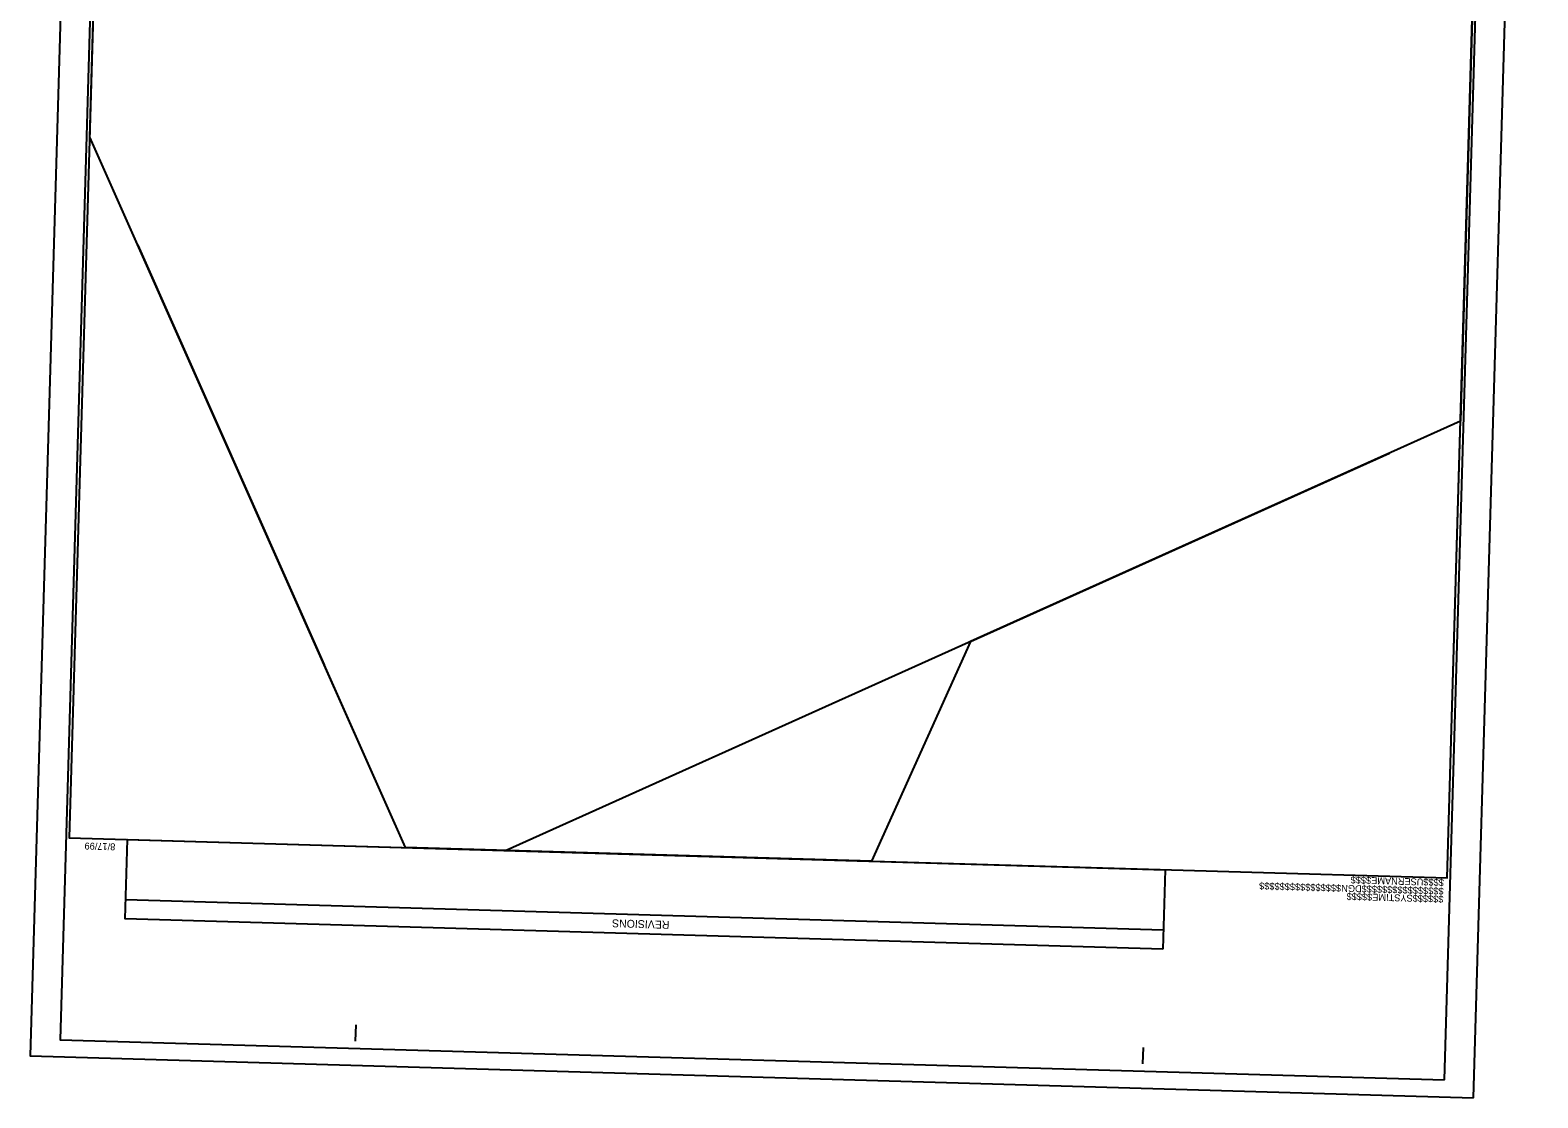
# Model space of a CAD drawing. Extents: x 2097422 to 2097881, y 685612 to 686386.
# Drawn here: x 2097421.7 to 2097881.1, y 685612.1 to 685937.6 of the extents above; entities that cross this region are included whole.
import ezdxf

# ---------------------------------------------------------------- set-up
doc = ezdxf.new("R2010")
doc.units = 0
for name, color, linetype in [('Matchline', 7, 'Continuous'), ('Scratch_Level_0', 7, 'Continuous'), ('Sheet Block Revision CELL', 7, 'Continuous'), ('Sheet Layout Plan Border', 7, 'Continuous'), ('Sheet Plan And Profile CELL', 7, 'Continuous'), ('Sheet Plan CELL', 7, 'Continuous'), ('Sheet Plot Border Inside CELL', 7, 'Continuous'), ('Sheet Plot Border Outside CELL', 7, 'Continuous'), ('Sheet Profile CELL', 7, 'Continuous'), ('Sheet Profile Grid Major CELL', 7, 'Continuous')]:
    doc.layers.add(name, color=color, linetype=linetype)

msp = doc.modelspace()

# ---------------------------------------------------------------- linework, layer by layer
at = {"layer": 'Matchline'}
for p, q in [((2097454.49, 685872.06), (2097511.35, 685744.13)), ((2097708.28, 685751.24), (2097835.94, 685808.7))]:
    msp.add_line(p, q, dxfattribs=at)
at = {"layer": 'Scratch_Level_0'}
msp.add_lwpolyline([(2097511.35, 685744.13), (2097439.86, 685904.99), (2097448.76, 686211.16), (2097523.65, 686208.98), (2097524.1, 686224.27), (2097869.03, 686214.24), (2097857.52, 685818.41), (2097708.28, 685751.24), (2097678.12, 685684.29), (2097536.1, 685688.42)], close=True, dxfattribs=at)
at = {"layer": 'Sheet Block Revision CELL'}
msp.add_line((2097766.98, 685663.3), (2097450.85, 685672.49), dxfattribs=at)
msp.add_lwpolyline([(2097766.81, 685657.48), (2097450.68, 685666.67), (2097451.39, 685690.88), (2097767.51, 685681.69)], close=True, dxfattribs=at)
at = {"layer": 'Sheet Layout Plan Border'}
msp.add_lwpolyline([(2097566.72, 685687.53), (2097536.1, 685688.42), (2097439.86, 685904.99), (2097448.76, 686211.16), (2097459.26, 686210.85), (2097523.65, 686208.98), (2097524.1, 686224.27), (2097869.03, 686214.24), (2097857.52, 685818.41)], close=True, dxfattribs=at)
at = {"layer": 'Sheet Plot Border Inside CELL'}
msp.add_lwpolyline([(2097852.7, 685617.59), (2097872.08, 686283.91), (2097450.21, 686296.17), (2097430.84, 685629.85)], close=True, dxfattribs=at)
at = {"layer": 'Sheet Plot Border Outside CELL'}
msp.add_lwpolyline([(2097861.53, 685612.13), (2097881.1, 686285.45), (2097441.29, 686298.23), (2097421.72, 685624.92)], close=True, dxfattribs=at)
at = {"layer": 'Sheet Profile CELL'}
for p, q in [((2097853.48, 685679.19), (2097870.91, 686278.94)), ((2097853.48, 685679.19), (2097853.48, 685679.19)), ((2097853.48, 685679.19), (2097853.48, 685679.19)), ((2097853.48, 685679.19), (2097853.48, 685679.19)), ((2097853.48, 685679.19), (2097853.48, 685679.19)), ((2097853.48, 685679.19), (2097853.48, 685679.19)), ((2097853.48, 685679.19), (2097853.48, 685679.19)), ((2097853.48, 685679.19), (2097853.48, 685679.19)), ((2097520.89, 685629.44), (2097521.03, 685634.43)), ((2097760.79, 685622.46), (2097760.93, 685627.46))]:
    msp.add_line(p, q, dxfattribs=at)
msp.add_lwpolyline([(2097451.09, 686291.14), (2097433.65, 685691.4), (2097853.48, 685679.19), (2097870.91, 686278.94)], close=True, dxfattribs=at)
msp.add_lwpolyline([(2097853.91, 685694.19), (2097853.91, 685694.19)], dxfattribs=at)
at = {"layer": 'Sheet Profile Grid Major CELL'}
msp.add_line((2097843.48, 685679.48), (2097843.48, 685679.48), dxfattribs=at)

# ---------------------------------------------------------------- texts
at = {"layer": 'Sheet Block Revision CELL'}
msp.add_text('REVISIONS', height=2.4, rotation=178.3348, dxfattribs=at).set_placement((2097616.53, 685666.05))
at = {"layer": 'Sheet Plan And Profile CELL'}
msp.add_text('8/17/99', height=2.1, rotation=178.3348, dxfattribs=at).set_placement((2097447.69, 685689.69))
at = {"layer": 'Sheet Plan CELL'}
for s, p in [('$$$$USERNAME$$$$', (2097852.51, 685678.79)), ('$$$$$$$$$$$$$$$$DGN$$$$$$$$$$$$$$$$', (2097852.44, 685676.17)), ('$$$$$$SYSTIME$$$$$', (2097852.38, 685673.74))]:
    msp.add_text(s, height=2.1, rotation=178.3348, dxfattribs=at).set_placement(p)

doc.saveas('drawing.dxf')
